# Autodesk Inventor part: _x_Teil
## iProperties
Created: 2005-11
Part Number: _x_Teil
Document SubType Name: Modeling
Designer: IMA/Frank
Manufacturer: Standard
Standards Organization: Custom
Author: IMA/Frank
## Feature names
1. Drehung1 [Revolution]
